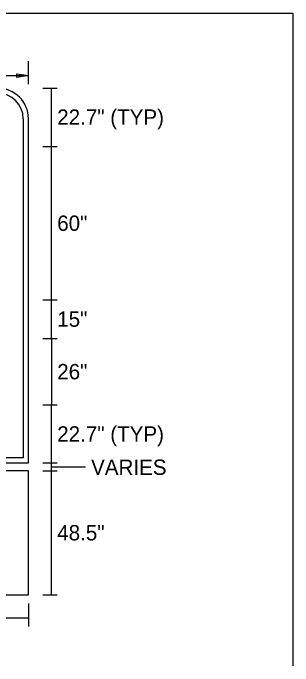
# Model space of a CAD drawing. Extents: x 10268312 to 10268472, y 2142583 to 2142688.
# Drawn here: x 10268458.14 to 10268470.98, y 2142657.53 to 2142687.53 of the extents above; entities that cross this region are included whole.
import ezdxf

# ---------------------------------------------------------------- set-up
doc = ezdxf.new("R2010")
doc.units = 0
for name, color, linetype in [('GSBWFill', 7, 'Continuous'), ('GSDims', 7, 'Continuous'), ('SignPanel', 7, 'Continuous'), ('SumBoxLines_dp', 7, 'Continuous')]:
    doc.layers.add(name, color=color, linetype=linetype)

msp = doc.modelspace()

# ---------------------------------------------------------------- linework, layer by layer
at = {"layer": 'GSBWFill'}
for p, q in [((10268458.845, 2142684.26), (10268458.845, 2142685.318)), ((10268458.61, 2142682.673), (10268458.61, 2142667.092))]:
    msp.add_line(p, q, dxfattribs=at)
msp.add_lwpolyline([(10268458.61, 2142667.092), (10268433.687, 2142667.092), (10268433.687, 2142666.857), (10268458.845, 2142666.857), (10268458.845, 2142666.857), (10268458.845, 2142682.673)], dxfattribs=at)
for radius in [1.411, 1.176]:
    msp.add_arc((10268457.434, 2142682.673), radius, 0, 90, dxfattribs=at)
at = {"layer": 'GSDims'}
for p, q in [((10268433.445, 2142684.657), (10268458.845, 2142684.657)), ((10268459.507, 2142684.084), (10268460.168, 2142684.084)), ((10268459.904, 2142681.415), (10268459.904, 2142684.084)), ((10268460.168, 2142684.084), (10268460.168, 2142684.084)), ((10268459.507, 2142681.403), (10268460.168, 2142681.403)), ((10268459.904, 2142674.349), (10268459.904, 2142681.415)), ((10268459.507, 2142674.349), (10268460.168, 2142674.349)), ((10268459.904, 2142672.584), (10268459.904, 2142674.349)), ((10268459.507, 2142672.583), (10268460.168, 2142672.583)), ((10268459.904, 2142672.583), (10268459.904, 2142669.526)), ((10268459.507, 2142669.526), (10268460.168, 2142669.526)), ((10268459.904, 2142666.857), (10268459.904, 2142669.526)), ((10268459.507, 2142666.857), (10268460.168, 2142666.857)), ((10268459.904, 2142666.504), (10268459.904, 2142666.857)), ((10268459.507, 2142666.504), (10268460.168, 2142666.504)), ((10268459.904, 2142666.68), (10268461.464, 2142666.68)), ((10268459.904, 2142660.8), (10268459.904, 2142666.504)), ((10268459.507, 2142660.8), (10268460.168, 2142660.8)), ((10268458.845, 2142660.403), (10268458.845, 2142659.345)), ((10268455.67, 2142659.742), (10268458.845, 2142659.742))]:
    msp.add_line(p, q, dxfattribs=at)
msp.add_lwpolyline([(10268458.845, 2142684.657), (10268458.316, 2142684.569), (10268458.316, 2142684.745)], close=True, dxfattribs=at)
at = {"layer": 'SignPanel'}
for p, q in [((10268458.845, 2142666.504), (10268433.445, 2142666.504)), ((10268458.845, 2142660.8), (10268458.845, 2142666.504)), ((10268433.445, 2142660.8), (10268458.845, 2142660.8))]:
    msp.add_line(p, q, dxfattribs=at)
at = {"layer": 'SumBoxLines_dp'}
for p, q in [((10268418.73, 2142687.532), (10268470.98, 2142687.532)), ((10268470.98, 2142687.532), (10268470.98, 2142657.532))]:
    msp.add_line(p, q, dxfattribs=at)

# ---------------------------------------------------------------- texts
at = {"layer": 'GSDims'}
for s, height, p in [('22.7" (TYP)', 0.70558, (10268460.168, 2142682.397)), ('60"', 0.7056, (10268460.168, 2142677.523)), ('15"', 0.7056, (10268460.168, 2142673.114)), ('26"', 0.7056, (10268460.168, 2142670.702)), ('22.7" (TYP)', 0.70558, (10268460.168, 2142667.838)), ('VARIES', 0.7056, (10268461.721, 2142666.31)), ('48.5"', 0.7056, (10268460.168, 2142663.299))]:
    msp.add_text(s, height=height, dxfattribs=at).set_placement(p)

doc.saveas('drawing.dxf')
